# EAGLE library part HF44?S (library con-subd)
SUB-D
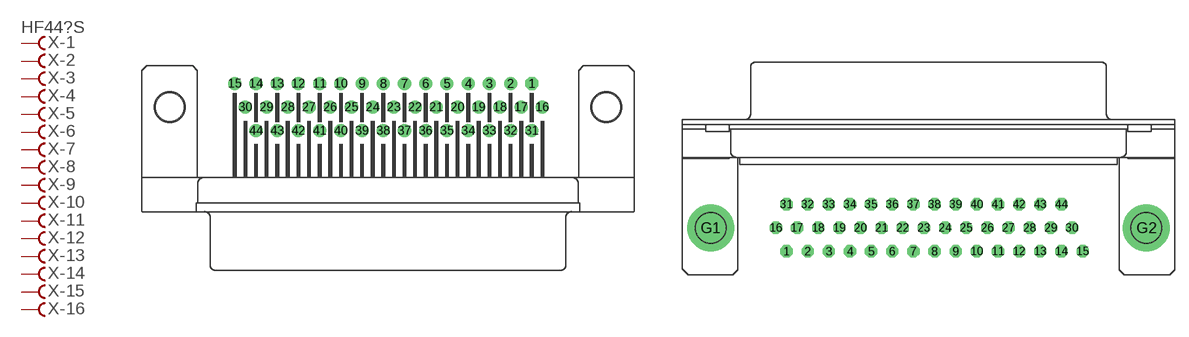
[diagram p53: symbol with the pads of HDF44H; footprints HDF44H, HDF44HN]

Designator prefix X; gates -1=FV -2=F -3=F -4=F -5=F -6=F -7=F -8=F -9=F -10=F -11=F -12=F -13=F -14=F -15=F -16=F -17=F -18=F -19=F -20=F -21=F -22=F -23=F -24=F -25=F -26=F -27=F -28=F -29=F -30=F -31=F -32=F -33=F -34=F -35=F -36=F -37=F -38=F -39=F -40=F -41=F -42=F -43=F -44=F

## HF44HS (OC_FARNELL: unknown; OC_NEWARK: unknown)  [HDF44H]
1  -1:F  pas
2  -2:F  pas
3  -3:F  pas
4  -4:F  pas
5  -5:F  pas
6  -6:F  pas
7  -7:F  pas
8  -8:F  pas
9  -9:F  pas
10  -10:F  pas
11  -11:F  pas
12  -12:F  pas
13  -13:F  pas
14  -14:F  pas
15  -15:F  pas
16  -16:F  pas
17  -17:F  pas
18  -18:F  pas
19  -19:F  pas
20  -20:F  pas
21  -21:F  pas
22  -22:F  pas
23  -23:F  pas
24  -24:F  pas
25  -25:F  pas
26  -26:F  pas
27  -27:F  pas
28  -28:F  pas
29  -29:F  pas
30  -30:F  pas
31  -31:F  pas
32  -32:F  pas
33  -33:F  pas
34  -34:F  pas
35  -35:F  pas
36  -36:F  pas
37  -37:F  pas
38  -38:F  pas
39  -39:F  pas
40  -40:F  pas
41  -41:F  pas
42  -42:F  pas
43  -43:F  pas
44  -44:F  pas

## HF44HNS (OC_FARNELL: unknown; OC_NEWARK: unknown)  [HDF44HN]
Pads as for HDF44H

## HF44VS (OC_FARNELL: unknown; OC_NEWARK: unknown)  [HDF44V]
Pads as for HDF44H

## Footprint HDF44H (pad centres in mm)
SUB-D
drill 0.9 octagon: 1 15.497,2.54
drill 0.9 round: 2 13.211,2.54; 3 10.925,2.54; 4 8.639,2.54; 5 6.353,2.54; 6 4.067,2.54; 7 1.781,2.54; 8 -0.505,2.54; 9 -2.791,2.54; 10 -5.077,2.54; 11 -7.363,2.54; 12 -9.649,2.54; 13 -11.935,2.54; 14 -14.221,2.54; 15 -16.507,2.54; 16 16.64,0; 17 14.354,0; 18 12.068,0; 19 9.782,0; 20 7.496,0; 21 5.21,0; 22 2.924,0; 23 0.638,0; 24 -1.648,0; 25 -3.934,0; 26 -6.22,0; 27 -8.506,0; 28 -10.792,0; 29 -13.078,0; 30 -15.364,0; 31 15.497,-2.54; 32 13.211,-2.54; 33 10.925,-2.54; 34 8.639,-2.54; 35 6.353,-2.54; 36 4.067,-2.54; 37 1.781,-2.54; 38 -0.505,-2.54; 39 -2.791,-2.54; 40 -5.077,-2.54; 41 -7.363,-2.54; 42 -9.649,-2.54; 43 -11.935,-2.54; 44 -14.221,-2.54
hole 3 at -23.52,0
hole 3 at 23.52,0

## Footprint HDF44HN (pad centres in mm)
SUB-D
drill 0.813 octagon: 1 -14.732,-3.81; 2 -12.446,-3.81; 3 -10.16,-3.81; 4 -7.874,-3.81; 5 -5.588,-3.81; 6 -3.302,-3.81; 7 -1.016,-3.81; 8 1.27,-3.81; 9 3.556,-3.81; 10 5.842,-3.81; 11 8.128,-3.81; 12 10.414,-3.81; 13 12.7,-3.81; 14 14.986,-3.81; 15 17.272,-3.81; 16 -15.875,-1.27; 17 -13.589,-1.27; 18 -11.303,-1.27; 19 -9.017,-1.27; 20 -6.731,-1.27; 21 -4.445,-1.27; 22 -2.159,-1.27; 23 0.127,-1.27; 24 2.413,-1.27; 25 4.699,-1.27; 26 6.985,-1.27; 27 9.271,-1.27; 28 11.557,-1.27; 29 13.843,-1.27; 30 16.129,-1.27; 31 -14.732,1.27; 32 -12.446,1.27; 33 -10.16,1.27; 34 -7.874,1.27; 35 -5.588,1.27; 36 -3.302,1.27; 37 -1.016,1.27; 38 1.27,1.27; 39 3.556,1.27; 40 5.842,1.27; 41 8.128,1.27; 42 10.414,1.27; 43 12.7,1.27; 44 14.986,1.27
drill 3.302 pad 5.08 round: G1 -22.936,-1.27; G2 24.166,-1.27

## Footprint HDF44V (pad centres in mm)
SUB-D
drill 0.9 octagon: 1 15.516,1.98
drill 0.9 round: 2 13.23,1.98; 3 10.944,1.98; 4 8.658,1.98; 5 6.372,1.98; 6 4.086,1.98; 7 1.8,1.98; 8 -0.486,1.98; 9 -2.772,1.98; 10 -5.058,1.98; 11 -7.344,1.98; 12 -9.63,1.98; 13 -11.916,1.98; 14 -14.202,1.98; 15 -16.488,1.98; 16 16.659,0; 17 14.373,0; 18 12.087,0; 19 9.801,0; 20 7.515,0; 21 5.229,0; 22 2.943,0; 23 0.657,0; 24 -1.629,0; 25 -3.915,0; 26 -6.201,0; 27 -8.487,0; 28 -10.773,0; 29 -13.059,0; 30 -15.345,0; 31 15.516,-1.98; 32 13.23,-1.98; 33 10.944,-1.98; 34 8.658,-1.98; 35 6.372,-1.98; 36 4.086,-1.98; 37 1.8,-1.98; 38 -0.486,-1.98; 39 -2.772,-1.98; 40 -5.058,-1.98; 41 -7.344,-1.98; 42 -9.63,-1.98; 43 -11.916,-1.98; 44 -14.202,-1.98
hole 3 at -23.52,0
hole 3 at 23.52,0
